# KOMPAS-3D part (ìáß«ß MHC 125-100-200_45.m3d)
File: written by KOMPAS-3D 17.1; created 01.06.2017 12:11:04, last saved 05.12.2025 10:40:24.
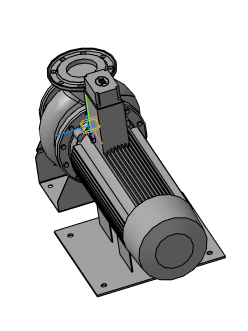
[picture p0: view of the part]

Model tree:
1. Операция без истории:1

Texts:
  ООО АДЛ ГРУПП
